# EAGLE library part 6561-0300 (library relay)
20 / 30 A-Leistungsrelais Source: http://www.finder.de/comuni/pdf/S65DE.pdf
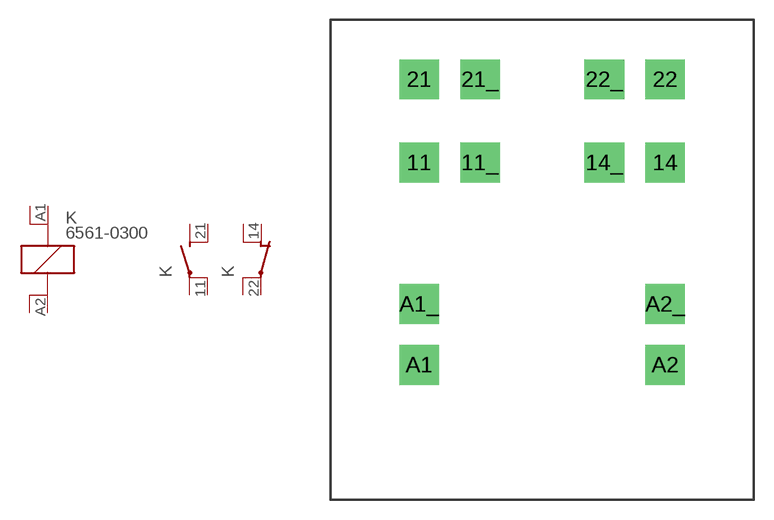
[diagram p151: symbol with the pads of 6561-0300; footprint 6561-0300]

Designator prefix K; gates 1=K-2P 2=S-2P -1=O-2P

## 6561-0300VAC6 (OC_FARNELL: unknown; OC_NEWARK: unknown), 6561-0300VAC12 (OC_FARNELL: unknown; OC_NEWARK: unknown), 6561-0300VAC24 (OC_FARNELL: unknown; OC_NEWARK: unknown), 6561-0300VAC48 (OC_FARNELL: unknown; OC_NEWARK: unknown), 6561-0300VAC60 (OC_FARNELL: unknown; OC_NEWARK: unknown), 6561-0300VAC110 (OC_FARNELL: unknown; OC_NEWARK: unknown), 6561-0300VAC120 (OC_FARNELL: unknown; OC_NEWARK: unknown), 6561-0300VAC230 (OC_FARNELL: unknown; OC_NEWARK: unknown), 6561-0300VAC240 (OC_FARNELL: unknown; OC_NEWARK: unknown), 6561-0300VAC400 (OC_FARNELL: unknown; OC_NEWARK: unknown), 6561-0300VDC6 (OC_FARNELL: unknown; OC_NEWARK: unknown), 6561-0300VDC12 (OC_FARNELL: unknown; OC_NEWARK: unknown), 6561-0300VDC24 (OC_FARNELL: unknown; OC_NEWARK: unknown), 6561-0300VDC48 (OC_FARNELL: unknown; OC_NEWARK: unknown), 6561-0300VDC60 (OC_FARNELL: unknown; OC_NEWARK: unknown), 6561-0300VDC110 (OC_FARNELL: unknown; OC_NEWARK: unknown), 6561-0300VDC125 (OC_FARNELL: unknown; OC_NEWARK: unknown), 6561-0300VDC220 (OC_FARNELL: unknown; OC_NEWARK: unknown)  [6561-0300]
11  2:P_  pas
11_  2:P  pas
14  -1:O  pas
14_  -1:O_  pas
21  2:S_  pas
21_  2:S  pas
22  -1:P  pas
22_  -1:P_  pas
A1  1:1_  pas
A1_  1:1  pas
A2  1:2_  pas
A2_  1:2  pas

## Footprint 6561-0300 (pad centres in mm)
20 / 30 A-Leistungsrelais Source: http://www.finder.de/comuni/pdf/S65DE.pdf
drill 2 pad 2.54 square: 11 -9.3,5; 11_ -4.7,5; 14 9.3,5; 14_ 4.7,5; 21 -9.3,11.3; 21_ -4.7,11.3; 22 9.3,11.3; 22_ 4.7,11.3; A1 -9.3,-10.3; A1_ -9.3,-5.7; A2 9.3,-10.3; A2_ 9.3,-5.7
